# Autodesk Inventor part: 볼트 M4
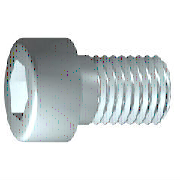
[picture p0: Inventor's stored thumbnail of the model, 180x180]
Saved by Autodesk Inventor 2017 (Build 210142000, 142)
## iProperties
IsCustomPart: 1
Created: 2012-02
Part Number: 볼트 M4
Material: 강철, 연강
Description: 6각머리 태핑 나사
Document SubType Name: Modeling
Standard: KS B 1003
Designer: mduedu
Standards Organization: KS
Language: ko-KR
Size Designation: M 4 x 10
Categories: <MemberInstance><Categories><Category DisplayName="조임쇠" InternalName="e4da775c-781d-43d5-af7c-5136215cf5a6" Mnemonic="FSTN"><Category DisplayName="볼트" InternalN
Density: 7.86 g/cm^3
Appearance: 강철
Mass: 2.0371 g
Surface Area: 3.0572 cm^2
Volume: 0.259174 cm^3
Author: mduedu
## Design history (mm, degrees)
sketch "스케치1"
  geometry: L1 (-1, 0)-(10, 0); L2 (10, 0)-(10, 2); L3 (10, 2)-(1.75, 2); L4 (1.75, 2)-(1.32, 2); L5 (1.32, 2)-(0, 2); L6 (0, 2)-(0, 3.5); L7 (0, 3.5)-(-4, 3.5); L8 (-4, 3.5)-(-4, 1.732); L9 (-4, 1.732)-(-2, 1.732); L10 (-2, 1.732)-(-1, 0); L11 (-6.8, 0)-(12.8, 0) reference; L12 (0, -0.7)-(0, 4.2) reference; L13 (1.75, 2)-(0, 2)
  constraints: 22 end point, 6 parallel, 2 collinear, 2 perpendicular, 1 horizontal, 1 point on line
  dimensions: "d1" = 8.25 distance from line of L3.end L2 (= GEL); "d2" = 0.42952 distance of L4.end L3.end (computed from GAL); "d3" = 4 distance between parallel lines of L8 L6 (= KOH); "d4" = 2 distance of L8.end L9.end (= INTI); "d5" = 60 deg angle of L10 L1; "d6" = 4 diameter of L3 L1 (= GD); "d7" = 4 diameter of L5 L1 (= BDM); "d8" = 3.4641 diameter of L9 L1 (= 1.1547 x SW); "d9" = 7 diameter of L7 L1 (= KOD); "d26" = 10 distance between parallel lines of L12 L2 (= NLG)
revolve "본체" sketch "스케치1" stored, may be unused: angle "d10" = 90 deg
sketch "스케치2"
  geometry: L1 (0, -4.9)-(0, 4.9) reference; L2 (-4.9, 0)-(4.9, 0) reference; L3 (1.732, 0)-(0.866, -1.5); L4 (0.866, -1.5)-(-0.866, -1.5); L5 (-0.866, -1.5)-(-1.732, 0); L6 (-1.732, 0)-(-0.866, 1.5); L7 (-0.866, 1.5)-(0.866, 1.5); L8 (0.866, 1.5)-(1.732, 0); 2 further points
  constraints: 12 end point, 1 coincident, 1 horizontal alignment, 1 point on line, 12 other
extrude "슬롯" join sketch "스케치2" stored distance "d11" = 10; taper "d12" = 0 deg
workplane "Work Plane1"
fillet "Fillet2" dims "d30" = 0.1 (= R)
body "Solid1"
fillet "모깎기1" dims "d17" = 0.4 (= RR)
feature "스레드" dims "d13" = 8.25 (= GEL), "d14" = 0
chamfer "모따기1" distance "d15" = 0.42941 (= -0.5 x SPD + 0.5 x GD); stored, may be unused: second distance "d16" = 0.42941 (= GUL), angle "d27" = 45 deg
other parameters: "GD" = 4 (= NND) [user parameter; used in 2 equation terms], "NLG" = 10 [user parameter; used in 1 equation term], "GEL" = 8.25 [user parameter; used in 2 equation terms], "KOD" = 7 [user parameter; used in 1 equation term], "KOH" = 4 [user parameter; used in 1 equation term], "INTI" = 2 [user parameter; used in 1 equation term], "GAL" = 0.42941 (= 0.61345 x PTC) [user parameter; used in 1 equation term], "GUL" = 0.42941 (= 0.61345 x PTC) [user parameter; used in 1 equation term], "BDM" = 4 (= NND) [user parameter; used in 1 equation term], "SW" = 3 [user parameter; used in 2 equation terms], "RR" = 0.4 [user parameter; used in 1 equation term], "SPD" = 3.14117 (= NND - 1.2269 x PTC) [user parameter; used in 1 equation term], "d19" = 0, "d28" = 0, "d29" = 0, "R" = 0.1 [user parameter; used in 1 equation term], "PHH" = 0.2 [user parameter], "GD1" = 3.14117 (= THREADDIA - 1.2269 x PTC) [user parameter], "THREADDIA" = 4 [user parameter; used in 1 equation term], "FAWI" = 45 deg [user parameter], "TPU" = 14.28571 (computed from PTC) [user parameter], "PTC" = 0.7 [user parameter; used in 5 equation terms], "NND" = 4 [user parameter; used in 3 equation terms], "TOA" = 30 deg [user parameter], "E0" = 3.465 (= 1.155 x SW) [user parameter]
